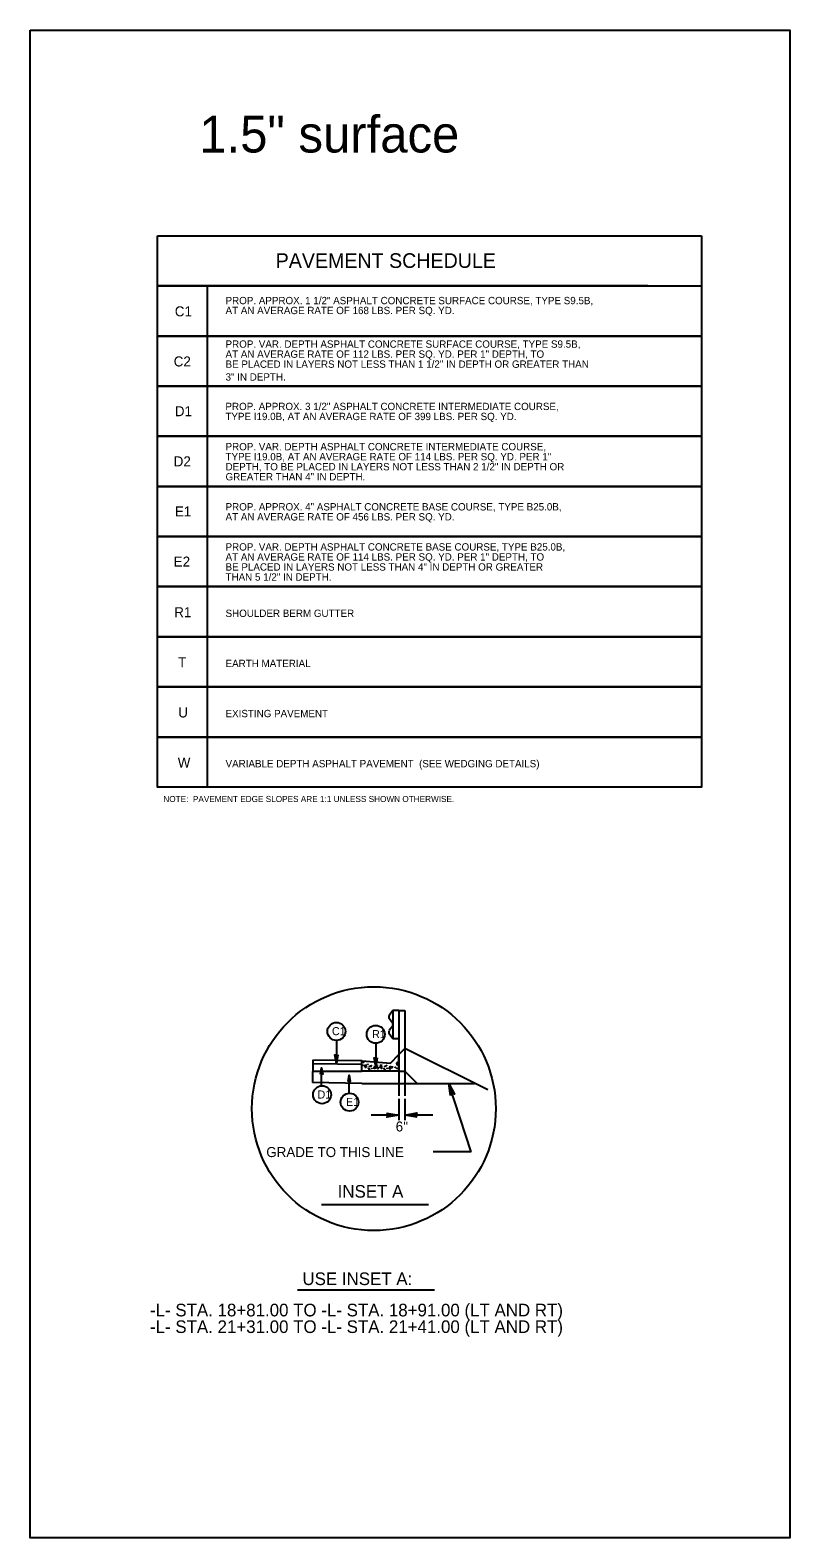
# Model space of a CAD drawing. Extents: x 1593595 to 1594166, y 741647 to 741854.
# Drawn here: x 1593771.4 to 1593833.5, y 741719.6 to 741842.9 of the extents above; entities that cross this region are included whole.
import ezdxf

# ---------------------------------------------------------------- set-up
doc = ezdxf.new("R2010")
doc.units = 0
for name, color, linetype in [('Default', 7, 'Continuous'), ('Prop Dimension', 7, 'Continuous'), ('Prop Pavement Schedule Description CELL', 7, 'Continuous'), ('Prop Terminator CELL', 7, 'Continuous'), ('Typical ID Circle CELL', 7, 'Continuous'), ('Typical Shoulder Slope CELL', 7, 'Continuous'), ('Typical Shoulder Slope Information CELL', 7, 'Continuous'), ('Typical Slope Point Local CELL', 7, 'Continuous'), ('Typical Terminator CELL', 7, 'Continuous'), ('Typical Text General CELL', 7, 'Continuous'), ('Typical Text ID Circle CELL', 7, 'Continuous'), ('Typical Text Label CELL', 7, 'Continuous')]:
    doc.layers.add(name, color=color, linetype=linetype)

msp = doc.modelspace()

# ---------------------------------------------------------------- linework, layer by layer
at = {"layer": 'Default'}
msp.add_lwpolyline([(1593785.9, 741809.68), (1593781.8, 741809.68), (1593781.8, 741813.78), (1593826.29, 741813.78), (1593826.29, 741809.68), (1593785.9, 741809.68), (1593785.9, 741813.78)], dxfattribs=at)
at = {"layer": 'Prop Dimension'}
for p, q in [((1593807.45, 741751.14), (1593805.63, 741756.75)), ((1593801.54, 741755.48), (1593801.54, 741753.75)), ((1593802.04, 741755.48), (1593802.04, 741753.75)), ((1593801.54, 741754.15), (1593799.29, 741754.15)), ((1593804.33, 741754.15), (1593802.04, 741754.15)), ((1593807.45, 741751.14), (1593804.35, 741751.14))]:
    msp.add_line(p, q, dxfattribs=at)
at = {"layer": 'Prop Pavement Schedule Description CELL'}
for p, q in [((1593781.8, 741821.98), (1593781.8, 741826.08)), ((1593781.8, 741826.08), (1593826.29, 741826.08)), ((1593826.29, 741826.08), (1593826.29, 741821.98)), ((1593785.9, 741821.98), (1593781.8, 741821.98)), ((1593821.9, 741821.98), (1593785.9, 741821.98)), ((1593785.9, 741817.88), (1593781.8, 741817.88)), ((1593821.9, 741817.88), (1593785.9, 741817.88))]:
    msp.add_line(p, q, dxfattribs=at)
for points in [[(1593785.9, 741817.88), (1593781.8, 741817.88), (1593781.8, 741821.98), (1593826.29, 741821.98), (1593826.29, 741817.88), (1593785.9, 741817.88), (1593785.9, 741821.98)], [(1593785.9, 741813.78), (1593781.8, 741813.78), (1593781.8, 741817.88), (1593826.29, 741817.88), (1593826.29, 741813.78), (1593785.9, 741813.78), (1593785.9, 741817.88)], [(1593785.9, 741805.58), (1593781.8, 741805.58), (1593781.8, 741809.68), (1593826.29, 741809.68), (1593826.29, 741805.58), (1593785.9, 741805.58), (1593785.9, 741809.68)], [(1593785.9, 741801.48), (1593781.8, 741801.48), (1593781.8, 741805.58), (1593826.29, 741805.58), (1593826.29, 741801.48), (1593785.9, 741801.48), (1593785.9, 741805.58)], [(1593785.9, 741797.38), (1593781.8, 741797.38), (1593781.8, 741801.48), (1593826.29, 741801.48), (1593826.29, 741797.38), (1593785.9, 741797.38), (1593785.9, 741801.48)], [(1593785.9, 741793.28), (1593781.8, 741793.28), (1593781.8, 741797.38), (1593826.29, 741797.38), (1593826.29, 741793.28), (1593785.9, 741793.28), (1593785.9, 741797.38)], [(1593785.9, 741789.18), (1593781.8, 741789.18), (1593781.8, 741793.28), (1593826.29, 741793.28), (1593826.29, 741789.18), (1593785.9, 741789.18), (1593785.9, 741793.28)], [(1593785.9, 741785.08), (1593781.8, 741785.08), (1593781.8, 741789.18), (1593826.29, 741789.18), (1593826.29, 741785.08), (1593785.9, 741785.08), (1593785.9, 741789.18)], [(1593785.9, 741780.98), (1593781.8, 741780.98), (1593781.8, 741785.08), (1593826.29, 741785.08), (1593826.29, 741780.98), (1593785.9, 741780.98), (1593785.9, 741785.08)]]:
    msp.add_lwpolyline(points, dxfattribs=at)
at = {"layer": 'Prop Terminator CELL'}
for points in [[(1593805.77, 741755.76), (1593805.63, 741756.75), (1593806.1, 741755.86), (1593805.9, 741755.93)], [(1593800.56, 741754.32), (1593801.54, 741754.15), (1593800.55, 741753.98), (1593800.68, 741754.15)], [(1593803.02, 741753.99), (1593802.04, 741754.15), (1593803.02, 741754.33), (1593802.9, 741754.15)]]:
    msp.add_lwpolyline(points, close=True, dxfattribs=at)
at = {"layer": 'Typical ID Circle CELL'}
for p, q in [((1593796.44, 741760.27), (1593796.44, 741758.37)), ((1593799.65, 741760.03), (1593799.65, 741758.13)), ((1593795.23, 741756.56), (1593795.23, 741758.02)), ((1593797.48, 741755.95), (1593797.48, 741757.42))]:
    msp.add_line(p, q, dxfattribs=at)
for centre in [(1593796.44, 741761), (1593799.65, 741760.76), (1593795.26, 741755.82), (1593797.51, 741755.21)]:
    msp.add_circle(centre, 0.734, dxfattribs=at)
at = {"layer": 'Typical Shoulder Slope CELL'}
for p, q in [((1593794.52, 741758.66), (1593794.48, 741756.83)), ((1593798.52, 741758.58), (1593794.52, 741758.66)), ((1593801.54, 741759.1), (1593802.04, 741759.6)), ((1593794.5, 741757.75), (1593798.52, 741757.75)), ((1593798.52, 741758.28), (1593794.51, 741758.36)), ((1593803.04, 741756.75), (1593802.04, 741757.75)), ((1593798.52, 741756.75), (1593794.47, 741756.83)), ((1593798.52, 741756.75), (1593807.74, 741756.75))]:
    msp.add_line(p, q, dxfattribs=at)
at = {"layer": 'Typical Slope Point Local CELL'}
for p, q in [((1593801.04, 741762.72), (1593800.75, 741762.31)), ((1593801.54, 741762.72), (1593801.04, 741762.72)), ((1593801.04, 741762.72), (1593801.04, 741760.4)), ((1593801.54, 741762.72), (1593801.54, 741757.75)), ((1593801.54, 741762.72), (1593802.04, 741762.72)), ((1593802.04, 741762.72), (1593802.04, 741757.75)), ((1593801.04, 741761.65), (1593800.75, 741762.06)), ((1593801.04, 741761.46), (1593800.75, 741761.06)), ((1593801.04, 741761.56), (1593801.04, 741761.65)), ((1593801.04, 741761.56), (1593801.04, 741761.46)), ((1593801.04, 741760.4), (1593800.75, 741760.8)), ((1593801.54, 741760.4), (1593801.04, 741760.4)), ((1593798.52, 741758.58), (1593798.52, 741758.58)), ((1593798.52, 741757.75), (1593798.52, 741758.56)), ((1593798.53, 741758.58), (1593800.85, 741758.41)), ((1593800.85, 741758.41), (1593801.54, 741759.1)), ((1593801.54, 741757.75), (1593801.54, 741759.1)), ((1593808.81, 741756.21), (1593802.04, 741759.6)), ((1593801.54, 741757.75), (1593798.52, 741757.75)), ((1593798.76, 741758.05), (1593798.84, 741758.29)), ((1593798.88, 741758.06), (1593798.76, 741758.05)), ((1593798.84, 741758.29), (1593798.88, 741758.06)), ((1593799.52, 741757.95), (1593799.58, 741758.18)), ((1593799.69, 741758.03), (1593799.52, 741757.95)), ((1593799.58, 741758.18), (1593799.69, 741758.03)), ((1593800.01, 741758.05), (1593800.09, 741758.29)), ((1593800.13, 741758.06), (1593800.01, 741758.05)), ((1593800.09, 741758.29), (1593800.13, 741758.06)), ((1593800.77, 741757.95), (1593800.83, 741758.18)), ((1593800.94, 741758.03), (1593800.77, 741757.95)), ((1593800.83, 741758.18), (1593800.94, 741758.03)), ((1593801.35, 741758.43), (1593801.37, 741758.25)), ((1593801.5, 741758.34), (1593801.35, 741758.43)), ((1593801.37, 741758.25), (1593801.5, 741758.34)), ((1593801.54, 741757.75), (1593802.04, 741757.75)), ((1593801.54, 741757.75), (1593801.54, 741755.73)), ((1593802.04, 741757.75), (1593802.04, 741755.73))]:
    msp.add_line(p, q, dxfattribs=at)
msp.add_lwpolyline([(1593771.39, 741842.9), (1593833.52, 741842.9), (1593833.52, 741719.57), (1593771.39, 741719.57)], close=True, dxfattribs=at)
msp.add_circle((1593799.5, 741754.68), 9.97, dxfattribs=at)
for centre, major_axis, start_param, end_param in [((1593800.8, 741762.18), (0, -0.155), 3.75251, 5.672516), ((1593800.8, 741760.93), (0, 0.155), 0.610968, 2.531366), ((1593798.53, 741758.56), (0, -0.0208), 3.105848, 4.712389)]:
    msp.add_ellipse(centre, major_axis=major_axis, ratio=0.5, start_param=start_param, end_param=end_param, dxfattribs=at)
for centre in [(1593798.65, 741758.47), (1593801.47, 741758.51), (1593798.61, 741758.22), (1593799.01, 741758.32), (1593799.07, 741757.97), (1593799.13, 741757.9), (1593799.16, 741758.15), (1593799.24, 741758.15), (1593799.29, 741758.21), (1593799.33, 741757.98), (1593799.53, 741758.06), (1593799.73, 741758.03), (1593799.75, 741758.13), (1593799.76, 741758.24), (1593799.82, 741757.96), (1593799.91, 741758.05), (1593800.01, 741758.07), (1593800.13, 741757.97), (1593800.32, 741757.97), (1593800.38, 741757.9), (1593800.41, 741758.15), (1593800.54, 741758.21), (1593800.58, 741757.98), (1593800.78, 741758.06), (1593800.81, 741757.85), (1593800.98, 741758.03), (1593801, 741758.13), (1593801.26, 741758.07), (1593801.38, 741757.97)]:
    msp.add_ellipse(centre, major_axis=(0, 0.016), ratio=0.5, dxfattribs=at)
at = {"layer": 'Typical Terminator CELL'}
for points in [[(1593796.56, 741759.08), (1593796.44, 741758.37), (1593796.31, 741759.09), (1593796.44, 741759)], [(1593796.56, 741759.08), (1593796.44, 741758.37), (1593796.31, 741759.09), (1593796.44, 741759)], [(1593799.77, 741758.84), (1593799.65, 741758.13), (1593799.52, 741758.85), (1593799.65, 741758.76)], [(1593795.14, 741757.5), (1593795.23, 741758.02), (1593795.33, 741757.49), (1593795.23, 741757.56)], [(1593797.39, 741756.89), (1593797.48, 741757.42), (1593797.57, 741756.89), (1593797.48, 741756.96)]]:
    msp.add_lwpolyline(points, close=True, dxfattribs=at)
at = {"layer": 'Typical Text Label CELL'}
for p, q in [((1593803.96, 741746.82), (1593795.23, 741746.82)), ((1593793.25, 741739.86), (1593804.46, 741739.86))]:
    msp.add_line(p, q, dxfattribs=at)

# ---------------------------------------------------------------- texts
at = {"layer": 'Default'}
for s, p in [('AT AN AVERAGE RATE OF 112 LBS. PER SQ. YD. PER 1" DEPTH, TO', (1593787.37, 741816.1)), ('PROP. VAR. DEPTH ASPHALT CONCRETE SURFACE COURSE, TYPE S9.5B,', (1593787.37, 741816.92)), ('BE PLACED IN LAYERS NOT LESS THAN 1 1/2" IN DEPTH OR GREATER THAN', (1593787.37, 741815.28)), ('3" IN DEPTH.', (1593787.37, 741814.23))]:
    msp.add_text(s, height=0.6, dxfattribs=at).set_placement(p)
at = {"layer": 'Prop Pavement Schedule Description CELL'}
for s, height, p in [('PAVEMENT SCHEDULE', 1.2, (1593791.47, 741823.45)), ('C1', 0.819, (1593783.22, 741819.49)), ('AT AN AVERAGE RATE OF 168 LBS. PER SQ. YD. ', 0.6, (1593787.37, 741819.67)), ('PROP. APPROX. 1 1/2" ASPHALT CONCRETE SURFACE COURSE, TYPE S9.5B, ', 0.6, (1593787.37, 741820.48)), ('C2', 0.819, (1593783.13, 741815.39)), ('D1', 0.819, (1593783.22, 741811.32)), ('TYPE I19.0B, AT AN AVERAGE RATE OF 399 LBS. PER SQ. YD.', 0.6, (1593787.36, 741811)), ('PROP. APPROX. 3 1/2" ASPHALT CONCRETE INTERMEDIATE COURSE,', 0.6, (1593787.36, 741811.82)), ('PROP. VAR. DEPTH ASPHALT CONCRETE INTERMEDIATE COURSE,', 0.6, (1593787.37, 741808.53)), ('D2', 0.819, (1593783.13, 741807.22)), ('TYPE I19.0B, AT AN AVERAGE RATE OF 114 LBS. PER SQ. YD. PER 1" ', 0.6, (1593787.37, 741807.71)), ('GREATER THAN 4" IN DEPTH.', 0.6, (1593787.37, 741806.07)), ('DEPTH, TO BE PLACED IN LAYERS NOT LESS THAN 2 1/2" IN DEPTH OR', 0.6, (1593787.37, 741806.89)), ('PROP. APPROX. 4" ASPHALT CONCRETE BASE COURSE, TYPE B25.0B,', 0.6, (1593787.37, 741803.61)), ('E1', 0.819, (1593783.22, 741803.12)), ('AT AN AVERAGE RATE OF 456 LBS. PER SQ. YD.', 0.6, (1593787.37, 741802.79)), ('PROP. VAR. DEPTH ASPHALT CONCRETE BASE COURSE, TYPE B25.0B,', 0.6, (1593787.37, 741800.33)), ('E2', 0.819, (1593783.13, 741799.02)), ('AT AN AVERAGE RATE OF 114 LBS. PER SQ. YD. PER 1" DEPTH, TO', 0.6, (1593787.37, 741799.51)), ('BE PLACED IN LAYERS NOT LESS THAN 4" IN DEPTH OR GREATER', 0.6, (1593787.37, 741798.69)), ('THAN 5 1/2" IN DEPTH.', 0.6, (1593787.37, 741797.87)), ('R1', 0.819, (1593783.17, 741794.88)), ('SHOULDER BERM GUTTER', 0.6, (1593787.37, 741794.9)), ('T', 0.819, (1593783.49, 741790.78)), ('EARTH MATERIAL', 0.6, (1593787.37, 741790.8)), ('U', 0.819, (1593783.5, 741786.68)), ('EXISTING PAVEMENT', 0.6, (1593787.37, 741786.7)), ('W', 0.819, (1593783.46, 741782.58)), ('VARIABLE DEPTH ASPHALT PAVEMENT  (SEE WEDGING DETAILS)', 0.6, (1593787.37, 741782.6)), ('NOTE:  PAVEMENT EDGE SLOPES ARE 1:1 UNLESS SHOWN OTHERWISE.', 0.5011, (1593782.28, 741779.76))]:
    msp.add_text(s, height=height, dxfattribs=at).set_placement(p)
at = {"layer": 'Typical Shoulder Slope Information CELL'}
msp.add_text('6"', height=0.818, rotation=358.8543, dxfattribs=at).set_placement((1593801.28, 741752.82))
at = {"layer": 'Typical Slope Point Local CELL'}
msp.add_text('1.5" surface', height=3, dxfattribs=at).set_placement((1593785.22, 741832.89))
at = {"layer": 'Typical Text General CELL'}
msp.add_text('GRADE TO THIS LINE', height=0.8181, dxfattribs=at).set_placement((1593790.7, 741750.72))
at = {"layer": 'Typical Text ID Circle CELL'}
for s, p in [('C1', (1593796.07, 741760.69)), ('R1', (1593799.35, 741760.45)), ('D1', (1593794.89, 741755.51)), ('E1', (1593797.22, 741754.9))]:
    msp.add_text(s, height=0.657, dxfattribs=at).set_placement(p)
at = {"layer": 'Typical Text Label CELL'}
for s, p in [('INSET A  ', (1593796.54, 741747.4)), ('-L- STA. 18+81.00 TO -L- STA. 18+91.00 (LT AND RT)', (1593781.19, 741737.69)), ('-L- STA. 21+31.00 TO -L- STA. 21+41.00 (LT AND RT)', (1593781.19, 741736.33))]:
    msp.add_text(s, height=1.033, dxfattribs=at).set_placement(p)
msp.add_text('USE INSET A:', height=1.033, rotation=360, dxfattribs=at).set_placement((1593793.66, 741740.25))

doc.saveas('drawing.dxf')
